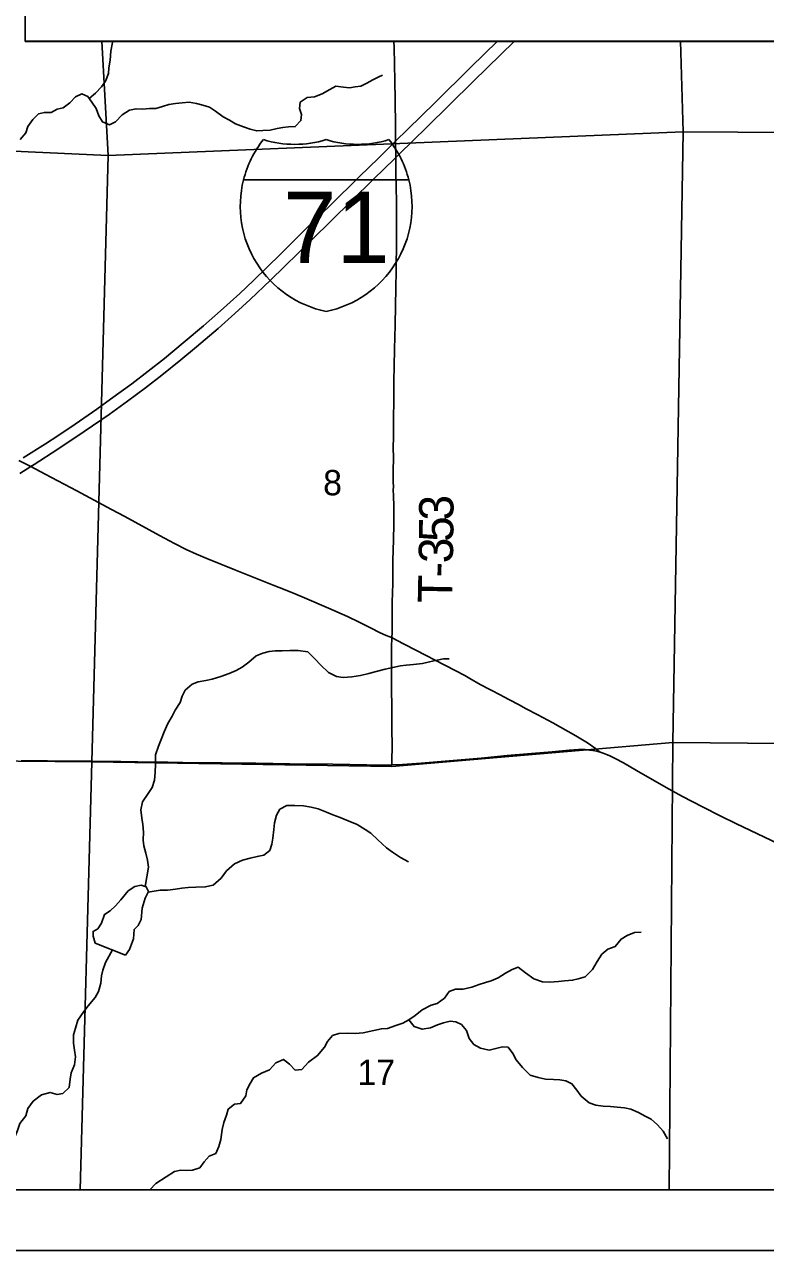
# Model space of a CAD drawing. Extents: x 0 to 34, y 0 to 22.
# Drawn here: x 4.127 to 5.352, y 14 to 16.027 of the extents above; entities that cross this region are included whole.
import ezdxf

# ---------------------------------------------------------------- set-up
doc = ezdxf.new("R2010")
doc.units = 0
for name, color, linetype in [('Default', 7, 'Continuous'), ('GM_X_County_Road', 7, 'Continuous'), ('GM_X_Interstate_Location', 7, 'Continuous'), ('GM_X_Interstate_Route', 7, 'Continuous'), ('GM_X_Interstate_Shield', 7, 'Continuous'), ('GM_X_Minor_Lake', 7, 'Continuous'), ('GM_X_Minor_River', 7, 'Continuous'), ('GM_X_Section', 7, 'Continuous'), ('GM_X_Section_Text', 7, 'Continuous'), ('GM_X_Township_Road', 7, 'Continuous'), ('GM_X_Township_Road_Text', 7, 'Continuous'), ('SH_Cut_Line', 7, 'Continuous'), ('SH_Data', 7, 'Continuous'), ('SH_Text', 7, 'Continuous')]:
    doc.layers.add(name, color=color, linetype=linetype)

msp = doc.modelspace()

# ---------------------------------------------------------------- linework, layer by layer
at = {"layer": 'Default'}
for points in [[(4.1282, 16.747), (6.0818, 16.747), (6.0818, 15.9995), (4.1282, 15.9995)], [(4.2188, 14.1), (5.1928, 14.1), (5.1991, 14.84), (4.7346, 14.8001), (4.2381, 14.8083)], [(5.1928, 14.1), (6.1826, 14.1), (6.1854, 14.8314), (5.1991, 14.84)], [(3.1977, 14.1), (4.2188, 14.1), (4.2381, 14.8083), (3.2026, 14.8175)]]:
    msp.add_lwpolyline(points, close=True, dxfattribs=at)
at = {"layer": 'GM_X_County_Road'}
for points in [[(4.7344, 14.8031), (4.752, 14.8039), (4.783, 14.8061), (4.882, 14.8144), (4.9253, 14.8183), (4.9656, 14.8216), (4.9996, 14.8247), (5.0274, 14.8274), (5.0429, 14.8283), (5.054, 14.8283), (5.0612, 14.8276), (5.0669, 14.8268), (5.0732, 14.8255), (5.0787, 14.824)], [(5.0787, 14.824), (5.0839, 14.8223), (5.0896, 14.8201), (5.0939, 14.8183), (5.1039, 14.8135), (5.1176, 14.8062), (5.1391, 14.7939), (5.1687, 14.7768), (5.193, 14.763), (5.2148, 14.751), (5.2479, 14.7337), (5.2784, 14.7184), (5.3035, 14.706), (5.3736, 14.6725), (5.421, 14.6494), (5.4546, 14.6331), (5.4967, 14.6131), (5.5191, 14.6023), (5.5581, 14.5833), (5.5861, 14.5697), (5.6225, 14.5522), (5.6589, 14.5347), (5.6896, 14.5198), (5.6949, 14.5172)], [(4.1217, 14.8097), (4.1652, 14.8095), (4.218, 14.8092), (4.2396, 14.8092), (4.2706, 14.8087), (4.2861, 14.8084), (4.3141, 14.808), (4.3358, 14.8077), (4.3638, 14.8073), (4.3886, 14.807), (4.4227, 14.8065), (4.4538, 14.8064), (4.4879, 14.8061), (4.5096, 14.8057), (4.5656, 14.8049), (4.637, 14.804), (4.6929, 14.8031), (4.7147, 14.8027), (4.7333, 14.803), (4.7344, 14.8031)]]:
    msp.add_lwpolyline(points, dxfattribs=at)
at = {"layer": 'GM_X_Interstate_Route'}
for points in [[(4.1191, 15.2849), (4.1373, 15.2963), (4.1428, 15.2997), (4.1818, 15.3252), (4.2257, 15.3545), (4.2667, 15.3827), (4.297, 15.4043), (4.3268, 15.4266), (4.3538, 15.4476), (4.3853, 15.4728), (4.4116, 15.4946), (4.4471, 15.5249), (4.475, 15.5496), (4.5001, 15.5727), (4.5338, 15.6048), (4.6028, 15.672), (4.6671, 15.7353), (4.7047, 15.7724), (4.7381, 15.8049), (4.7408, 15.8075), (4.7471, 15.8135), (4.7915, 15.857), (4.8691, 15.9332), (4.9372, 16)], [(4.1245, 15.3109), (4.1614, 15.334), (4.1823, 15.3475), (4.2107, 15.3666), (4.2463, 15.3915), (4.2691, 15.4078), (4.3043, 15.4335), (4.3315, 15.4541), (4.3584, 15.4754), (4.3896, 15.501), (4.4229, 15.5291), (4.4509, 15.5537), (4.4832, 15.5829), (4.5059, 15.6042), (4.5504, 15.6476), (4.5923, 15.6893), (4.6056, 15.7023), (4.6324, 15.7282), (4.681, 15.7763), (4.7121, 15.8067), (4.7366, 15.8306), (4.7405, 15.8344), (4.761, 15.8545), (4.8054, 15.898), (4.8653, 15.9568), (4.9093, 16)], [(3.2011, 14.1), (8.2568, 14.1)]]:
    msp.add_lwpolyline(points, dxfattribs=at)
at = {"layer": 'GM_X_Interstate_Shield'}
for p, q in [((4.4892, 15.7706), (4.7624, 15.7706)), ((4.7624, 15.7706), (4.4892, 15.7706)), ((4.7624, 15.7706), (4.4892, 15.7706))]:
    msp.add_line(p, q, dxfattribs=at)
for centre, start, end in [((4.6613, 15.727), 141.669, 165.8066), ((4.5739, 16.0069), 253.0091, 286.9909), ((4.6777, 16.0069), 253.0091, 286.9909), ((4.5903, 15.727), 14.1934, 38.331), ((4.6613, 15.727), 165.8066, 258.463), ((4.5903, 15.727), 281.537, 14.1934)]:
    msp.add_arc(centre, 0.1776, start, end, dxfattribs=at)
at = {"layer": 'GM_X_Minor_Lake'}
for points in [[(4.2939, 14.4886), (4.3007, 14.4977), (4.3071, 14.5152), (4.3085, 14.5308), (4.315, 14.5376), (4.3199, 14.5471), (4.3213, 14.5661), (4.3266, 14.5824), (4.3319, 14.5935), (4.3284, 14.6014), (4.3197, 14.604), (4.3095, 14.6021), (4.2985, 14.5949), (4.2864, 14.58), (4.2777, 14.5698), (4.2686, 14.5618), (4.2595, 14.5557), (4.2543, 14.5412), (4.2482, 14.5321), (4.2403, 14.5275), (4.2407, 14.5196), (4.2437, 14.5082)], [(4.2437, 14.5082), (4.2939, 14.4886)]]:
    msp.add_lwpolyline(points, dxfattribs=at)
at = {"layer": 'GM_X_Minor_River'}
for points in [[(4.234, 15.9049), (4.2443, 15.914), (4.2542, 15.9242), (4.2611, 15.934), (4.2658, 15.9464), (4.2666, 15.9559), (4.2686, 15.9684), (4.2699, 15.9836), (4.2727, 15.9976), (4.2746, 16)], [(4.1198, 15.8374), (4.129, 15.8483), (4.1325, 15.8586), (4.1406, 15.8702), (4.1501, 15.8796), (4.16, 15.8822), (4.171, 15.8817), (4.1812, 15.8873), (4.1907, 15.8899), (4.2018, 15.8977), (4.2113, 15.9079), (4.2216, 15.9127), (4.2314, 15.9084), (4.2385, 15.8989), (4.2456, 15.8886), (4.2497, 15.8764), (4.2557, 15.8668), (4.2677, 15.8614), (4.2776, 15.8663), (4.2883, 15.8779), (4.3005, 15.8861), (4.3115, 15.8883), (4.3228, 15.8874), (4.3335, 15.8885), (4.3441, 15.8887), (4.3551, 15.8921), (4.3657, 15.895), (4.3767, 15.8968), (4.3877, 15.8978), (4.3991, 15.8992), (4.4115, 15.8968), (4.4217, 15.8941), (4.4327, 15.8909), (4.4429, 15.884), (4.4557, 15.8748), (4.4658, 15.8693), (4.476, 15.8632), (4.4892, 15.8581), (4.5002, 15.8542), (4.5111, 15.8514), (4.521, 15.8521), (4.5331, 15.8528), (4.5445, 15.8553), (4.554, 15.8571), (4.5634, 15.8581), (4.5748, 15.8588), (4.584, 15.8686), (4.5848, 15.8788), (4.5819, 15.8887), (4.5827, 15.8989), (4.5945, 15.9068), (4.6063, 15.9078), (4.6192, 15.9126), (4.6317, 15.9201), (4.6416, 15.9257), (4.6545, 15.9237), (4.6643, 15.9228), (4.6738, 15.9242), (4.6833, 15.9253), (4.6932, 15.9305), (4.7031, 15.9361), (4.713, 15.9409), (4.719, 15.9435)], [(4.3263, 14.6021), (4.3318, 14.6341), (4.3306, 14.6454), (4.3275, 14.6568), (4.3241, 14.6693), (4.3233, 14.6788), (4.3236, 14.6917), (4.3228, 14.7042), (4.3209, 14.7148), (4.3193, 14.7285), (4.322, 14.7418), (4.3314, 14.7559), (4.3378, 14.7657), (4.342, 14.7779), (4.3431, 14.7904), (4.3438, 14.8041), (4.3433, 14.8196), (4.3486, 14.8341), (4.3531, 14.8451), (4.358, 14.8576), (4.3641, 14.8713), (4.3709, 14.8838), (4.3761, 14.8933), (4.3841, 14.9063), (4.3874, 14.9165), (4.3927, 14.9264), (4.4041, 14.9367), (4.4139, 14.9405), (4.4268, 14.9428), (4.4371, 14.9448), (4.4518, 14.949), (4.4655, 14.9543), (4.4768, 14.9589), (4.4871, 14.9646), (4.4977, 14.973), (4.5098, 14.9833), (4.5208, 14.9879), (4.5314, 14.9906), (4.5416, 14.9917), (4.553, 14.9918), (4.5659, 14.9922), (4.5796, 14.9922), (4.5955, 14.99), (4.6073, 14.9783), (4.6168, 14.9677), (4.6297, 14.9556), (4.6427, 14.9492), (4.654, 14.9477), (4.6681, 14.9485), (4.6825, 14.9508), (4.6961, 14.9539), (4.7086, 14.9573), (4.7234, 14.9616), (4.7359, 14.9643), (4.7488, 14.9669), (4.7583, 14.9681), (4.7704, 14.9693), (4.7849, 14.9709), (4.7966, 14.9732), (4.8065, 14.9758), (4.8197, 14.9782), (4.8292, 14.9782)], [(4.3316, 14.5928), (4.3512, 14.5958), (4.3634, 14.5958), (4.3766, 14.5974), (4.3872, 14.5989), (4.3975, 14.6001), (4.4104, 14.6009), (4.4259, 14.6013), (4.4392, 14.604), (4.4521, 14.6158), (4.4608, 14.6276), (4.4744, 14.6394), (4.4873, 14.6455), (4.5001, 14.649), (4.5119, 14.6513), (4.5229, 14.654), (4.5327, 14.6616), (4.5361, 14.6719), (4.5376, 14.6817), (4.5391, 14.6962), (4.5406, 14.7072), (4.5436, 14.7197), (4.5492, 14.7296), (4.561, 14.7357), (4.5739, 14.7361), (4.5883, 14.7354), (4.6012, 14.7331), (4.6126, 14.7301), (4.6266, 14.7249), (4.6369, 14.7207), (4.6487, 14.7162), (4.6623, 14.7106), (4.6768, 14.7042), (4.6901, 14.6962), (4.6999, 14.6902), (4.711, 14.6792), (4.7254, 14.666), (4.7353, 14.6588), (4.7486, 14.6497), (4.7619, 14.6429)], [(4.5425, 14.3103), (4.555, 14.316), (4.5649, 14.3081), (4.5748, 14.2979), (4.5858, 14.2994), (4.5964, 14.3112), (4.6115, 14.3223), (4.6232, 14.3363), (4.6281, 14.3458), (4.6364, 14.3557), (4.647, 14.3588), (4.6603, 14.3596), (4.6736, 14.3589), (4.6869, 14.3597), (4.7047, 14.3639), (4.7172, 14.3666), (4.7274, 14.367), (4.7411, 14.372), (4.7525, 14.3758), (4.7627, 14.3815), (4.7729, 14.3884), (4.7846, 14.3979), (4.7994, 14.4055), (4.8093, 14.4082), (4.8214, 14.417), (4.8293, 14.428), (4.8395, 14.4322), (4.8521, 14.4323), (4.8665, 14.4357), (4.879, 14.4399), (4.8892, 14.443), (4.8987, 14.4461), (4.9101, 14.451), (4.9222, 14.4586), (4.9332, 14.4648), (4.9434, 14.4686), (4.9556, 14.4591), (4.9692, 14.4493), (4.9837, 14.444), (4.9958, 14.4437), (5.0098, 14.4449), (5.0201, 14.4457), (5.0334, 14.4468), (5.0428, 14.4491), (5.0542, 14.4526), (5.0663, 14.4644), (5.0739, 14.4781), (5.0814, 14.4899), (5.0916, 14.4982), (5.1038, 14.5028), (5.1136, 14.515), (5.1234, 14.5211), (5.1359, 14.5261), (5.1469, 14.5265)], [(4.1553, 14.2571), (4.1693, 14.2613), (4.1807, 14.258), (4.1902, 14.2595), (4.2008, 14.2694), (4.2023, 14.2831), (4.2042, 14.2937), (4.2098, 14.307), (4.2113, 14.3203), (4.2097, 14.3313), (4.2082, 14.343), (4.2081, 14.3567), (4.2111, 14.3677), (4.2153, 14.381), (4.2251, 14.3951), (4.2323, 14.4046), (4.2436, 14.4183), (4.2493, 14.4285), (4.253, 14.4422), (4.2541, 14.454), (4.2564, 14.4635), (4.2609, 14.476), (4.2727, 14.4969)], [(4.7627, 14.3815), (4.7711, 14.3705), (4.7847, 14.3657), (4.7984, 14.368), (4.8101, 14.3729), (4.8196, 14.3764), (4.8306, 14.3791), (4.8401, 14.3783), (4.8496, 14.3738), (4.8576, 14.364), (4.8622, 14.3507), (4.8702, 14.3405), (4.8808, 14.3348), (4.8956, 14.3315), (4.9066, 14.3338), (4.9172, 14.3365), (4.9267, 14.3361), (4.9347, 14.3255), (4.94, 14.3153), (4.9503, 14.3024), (4.9629, 14.2899), (4.9765, 14.2858), (4.9883, 14.2835), (5.0016, 14.2828), (5.0122, 14.2821), (5.0221, 14.2806), (5.0323, 14.2757), (5.0403, 14.2651), (5.0476, 14.2549), (5.0609, 14.2443), (5.0719, 14.2405), (5.0837, 14.2387), (5.0958, 14.238), (5.1068, 14.2372), (5.1193, 14.2358), (5.1296, 14.2335), (5.1425, 14.2279), (5.1535, 14.2222), (5.163, 14.2169), (5.174, 14.2078), (5.1832, 14.1972), (5.19, 14.1847)], [(4.3341, 14.1), (4.3443, 14.1105), (4.3613, 14.1219), (4.375, 14.1307), (4.3852, 14.1326), (4.3951, 14.1323), (4.4049, 14.133), (4.4167, 14.1365), (4.4238, 14.1464), (4.4325, 14.1559), (4.4432, 14.1605), (4.4484, 14.1719), (4.4514, 14.1833), (4.454, 14.2), (4.4567, 14.2114), (4.4608, 14.2239), (4.4638, 14.2334), (4.4744, 14.2422), (4.4843, 14.2433), (4.493, 14.2559), (4.4944, 14.2654), (4.5001, 14.276), (4.5054, 14.2855), (4.5186, 14.2931), (4.5319, 14.2989), (4.5425, 14.3103)], [(4.0362, 14.1), (4.0363, 14.1), (4.045, 14.1096), (4.056, 14.1202), (4.0658, 14.1282), (4.0772, 14.1362), (4.0885, 14.1488), (4.0926, 14.1621), (4.0987, 14.172), (4.1089, 14.1826), (4.1153, 14.1982), (4.1194, 14.21), (4.1289, 14.2225), (4.1323, 14.2347), (4.1413, 14.2468), (4.1553, 14.2571)]]:
    msp.add_lwpolyline(points, dxfattribs=at)
at = {"layer": 'GM_X_Section'}
for points in [[(4.2148, 16.747), (4.2083, 16.8683), (4.1045, 16.8706), (3.2153, 16.8759), (3.2082, 15.8593), (4.2651, 15.8107), (4.2549, 16), (4.1282, 16), (4.1282, 16.747)], [(5.2115, 16), (5.2159, 15.85), (6.2093, 15.844), (6.1739, 16.8615), (6.1193, 16.8628), (5.1862, 16.8638), (5.1896, 16.747), (6.0753, 16.747), (6.0753, 16)], [(4.2549, 16), (4.2651, 15.8107), (5.2159, 15.85), (5.2115, 16)], [(3.2082, 15.8593), (4.2651, 15.8107), (4.2381, 14.8083), (3.2026, 14.8175), (3.2029, 14.8323), (3.2075, 15.8525)], [(5.2159, 15.85), (5.1991, 14.84), (4.7346, 14.8001), (4.2381, 14.8083), (4.2651, 15.8107)], [(5.2159, 15.85), (6.2093, 15.844), (6.1854, 14.8314), (5.1991, 14.84)]]:
    msp.add_lwpolyline(points, close=True, dxfattribs=at)
at = {"layer": 'GM_X_Township_Road'}
for points in [[(4.7415, 15.6206), (4.7416, 15.6266), (4.7422, 15.6638), (4.7422, 15.6918), (4.7422, 15.729), (4.7414, 15.7632), (4.741, 15.7787), (4.7408, 15.8035), (4.7408, 15.8075), (4.7405, 15.8315), (4.7405, 15.8344), (4.7403, 15.8594), (4.74, 15.9029), (4.7396, 15.9341), (4.7387, 15.962), (4.738, 15.9897), (4.7376, 16)], [(4.7345, 15.0136), (4.7347, 15.0222), (4.7352, 15.0719), (4.7358, 15.103), (4.7361, 15.134), (4.7362, 15.1433), (4.7364, 15.1557), (4.7369, 15.1774), (4.7375, 15.1991), (4.7376, 15.2084), (4.7375, 15.2208), (4.7375, 15.2301), (4.7375, 15.2362), (4.7374, 15.2423), (4.7373, 15.2453), (4.7373, 15.2484), (4.7368, 15.2573), (4.7369, 15.2632), (4.7367, 15.2705), (4.7367, 15.2796), (4.7367, 15.2902), (4.7372, 15.31), (4.7368, 15.3292), (4.737, 15.3441), (4.7372, 15.3565), (4.7372, 15.3789), (4.7377, 15.403), (4.7378, 15.438), (4.7383, 15.4626), (4.7387, 15.4908), (4.7397, 15.53), (4.7405, 15.5627), (4.741, 15.5907), (4.7415, 15.6206)], [(4.1173, 15.3065), (4.1363, 15.2968), (4.1373, 15.2963), (4.1612, 15.284), (4.2134, 15.2563), (4.271, 15.2256), (4.2928, 15.2137), (4.3501, 15.1823), (4.3748, 15.1691), (4.3942, 15.1593), (4.4111, 15.1515), (4.4283, 15.1443), (4.4745, 15.1258), (4.538, 15.1004), (4.5582, 15.0924), (4.5754, 15.0852), (4.5897, 15.0792), (4.6297, 15.0622), (4.661, 15.0482), (4.6806, 15.039), (4.7001, 15.0293), (4.714, 15.0222), (4.7253, 15.0172), (4.7309, 15.015), (4.7345, 15.0136)], [(4.7344, 14.8031), (4.7344, 14.808), (4.7347, 14.836), (4.7346, 14.8608), (4.7342, 14.8981), (4.734, 14.9291), (4.7339, 14.957), (4.7341, 14.9819), (4.7341, 14.9974), (4.7345, 15.0136)], [(4.7345, 15.0136), (4.7412, 15.0099), (4.8549, 14.9506)], [(4.8549, 14.9506), (4.8632, 14.946), (4.8807, 14.936), (4.8964, 14.9279), (4.9155, 14.9179)], [(4.9155, 14.9179), (4.9172, 14.9169), (4.9439, 14.9027), (4.9564, 14.8956), (4.9758, 14.8859), (5.0009, 14.8727), (5.0388, 14.851), (5.055, 14.8414), (5.0628, 14.8364), (5.0659, 14.8342), (5.0675, 14.8329), (5.0713, 14.83), (5.0748, 14.8271), (5.0787, 14.824)]]:
    msp.add_lwpolyline(points, dxfattribs=at)
at = {"layer": 'SH_Cut_Line'}
msp.add_lwpolyline([(2.1, 14.1), (8.2568, 14.1)], dxfattribs=at)
at = {"layer": 'SH_Data'}
for p, q in [((2.1, 14.1), (8.9, 14.1)), ((2, 14), (9, 14))]:
    msp.add_line(p, q, dxfattribs=at)
at = {"layer": 'SH_Text'}
msp.add_lwpolyline([(4.1282, 16.747), (6.0753, 16.747), (6.0753, 15.9995), (4.1282, 15.9995)], close=True, dxfattribs=at)

# ---------------------------------------------------------------- texts
at = {"layer": 'GM_X_Interstate_Location'}
for s in ['-', '.', ',']:
    msp.add_text(s, height=0.000189, dxfattribs=at).set_placement((4.6258, 15.695))
msp.add_text('71', height=0.000189, rotation=0, dxfattribs=at).set_placement((4.5871, 15.6558))
at = {"layer": 'GM_X_Interstate_Shield'}
msp.add_text('71', height=0.11837, dxfattribs=at).set_placement((4.5546, 15.6329))
at = {"layer": 'GM_X_Section_Text'}
for s, height, p in [('8', 0.0419, (4.6208, 15.2489)), ('17', 0.04186, (4.6775, 14.2736))]:
    msp.add_text(s, height=height, rotation=0, dxfattribs=at).set_placement(p)
at = {"layer": 'GM_X_Township_Road_Text'}
for s, rotation, p in [('3', 89.917, (4.8363, 15.2072)), ('5', 89.4074, (4.836, 15.1716)), ('3', 88.9705, (4.8353, 15.1362)), ('-', 88.8879, (4.8349, 15.1127)), ('T', 88.8685, (4.834, 15.0702))]:
    msp.add_text(s, height=0.0568, rotation=rotation, dxfattribs=at).set_placement(p)

doc.saveas('drawing.dxf')
